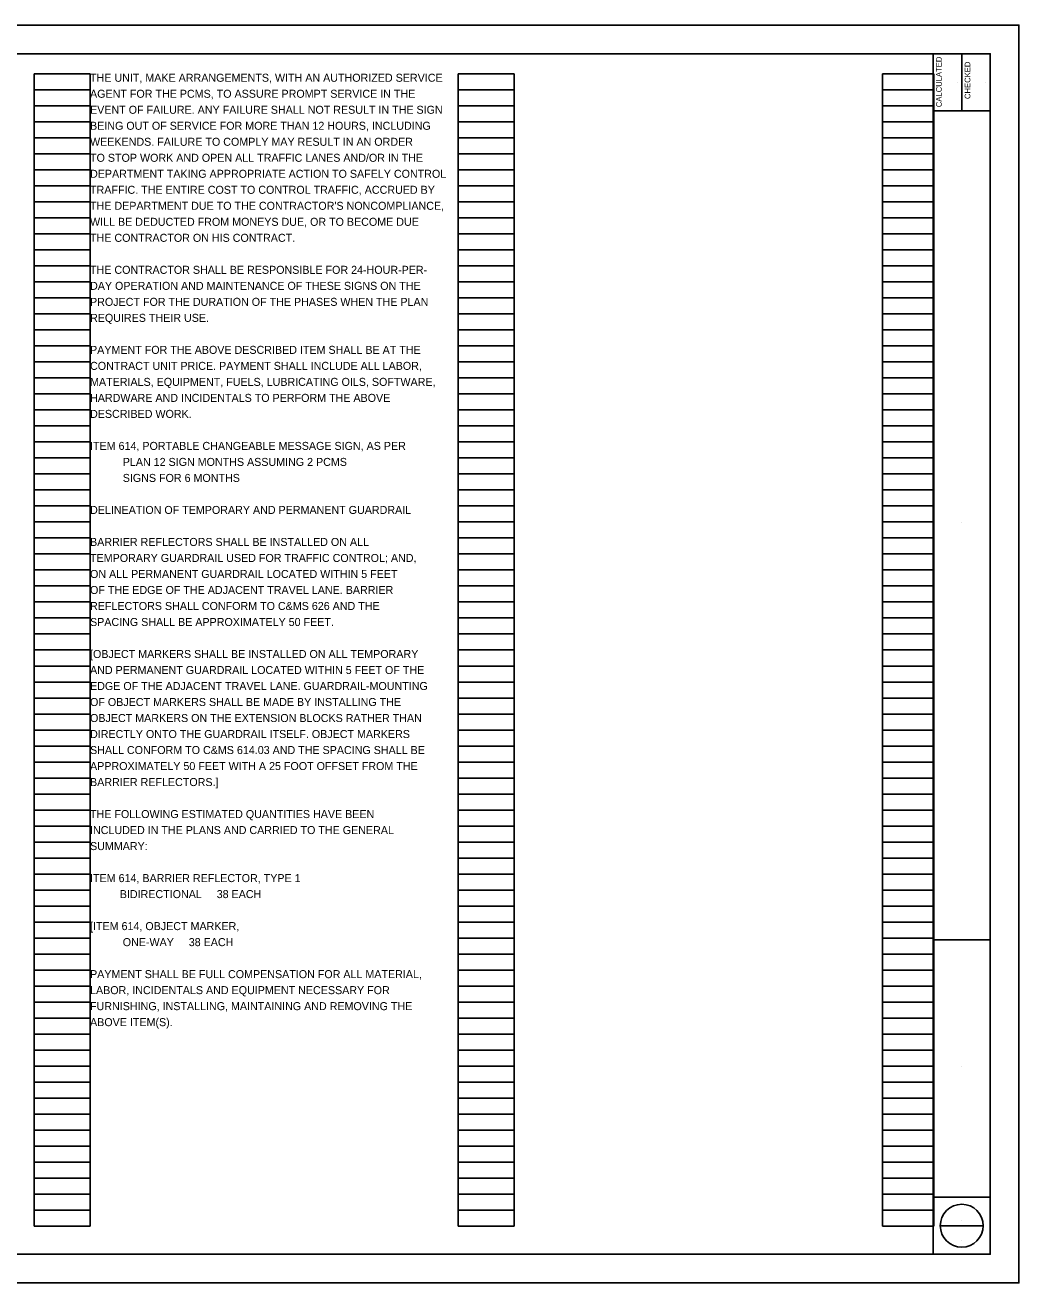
# Model space of a CAD drawing. Extents: x 0 to 34, y 0 to 22.
# Drawn here: x 16.62 to 34, y 0 to 22 of the extents above; entities that cross this region are included whole.
import ezdxf

# ---------------------------------------------------------------- set-up
doc = ezdxf.new("R2010")
doc.units = 0
for name, color, linetype in [('SH_Border', 7, 'Continuous'), ('SH_Cut_Line', 7, 'Continuous'), ('SH_Data', 7, 'Continuous'), ('SH_Text', 7, 'Continuous')]:
    doc.layers.add(name, color=color, linetype=linetype)

msp = doc.modelspace()

# ---------------------------------------------------------------- linework, layer by layer
at = {"layer": 'SH_Border'}
for p, q in [((32.5, 0.5), (32.5, 21.5)), ((33, 21.5), (33, 20.5)), ((32.5, 20.5), (33.5, 20.5)), ((32.5, 6), (33.5, 6)), ((32.5, 1.5), (33.5, 1.5))]:
    msp.add_line(p, q, dxfattribs=at)
msp.add_lwpolyline([(2, 21.5), (33.5, 21.5), (33.5, 0.5), (2, 0.5)], close=True, dxfattribs=at)
at = {"layer": 'SH_Cut_Line'}
msp.add_lwpolyline([(0, 0), (34, 0), (34, 22), (0, 22)], close=True, dxfattribs=at)
at = {"layer": 'SH_Data'}
for p, q in [((16.772, 0.99), (16.772, 21.15)), ((16.772, 21.15), (17.752, 21.15)), ((17.752, 0.99), (17.752, 21.15)), ((24.192, 0.99), (24.192, 21.15)), ((24.192, 21.15), (25.172, 21.15)), ((25.172, 0.99), (25.172, 21.15)), ((31.612, 0.99), (31.612, 21.15)), ((31.612, 21.15), (32.512, 21.15)), ((32.512, 0.99), (32.512, 21.15)), ((32.92, 21.004), (32.92, 21.004)), ((33.42, 21.004), (33.42, 21.004)), ((16.772, 20.87), (17.752, 20.87)), ((24.192, 20.87), (25.172, 20.87)), ((31.612, 20.87), (32.512, 20.87)), ((16.772, 20.59), (17.752, 20.59)), ((24.192, 20.59), (25.172, 20.59)), ((31.612, 20.59), (32.512, 20.59)), ((16.772, 20.31), (17.752, 20.31)), ((24.192, 20.31), (25.172, 20.31)), ((31.612, 20.31), (32.512, 20.31)), ((16.772, 20.03), (17.752, 20.03)), ((24.192, 20.03), (25.172, 20.03)), ((31.612, 20.03), (32.512, 20.03)), ((16.772, 19.75), (17.752, 19.75)), ((24.192, 19.75), (25.172, 19.75)), ((31.612, 19.75), (32.512, 19.75)), ((16.772, 19.47), (17.752, 19.47)), ((24.192, 19.47), (25.172, 19.47)), ((31.612, 19.47), (32.512, 19.47)), ((16.772, 19.19), (17.752, 19.19)), ((24.192, 19.19), (25.172, 19.19)), ((31.612, 19.19), (32.512, 19.19)), ((16.772, 18.91), (17.752, 18.91)), ((24.192, 18.91), (25.172, 18.91)), ((31.612, 18.91), (32.512, 18.91)), ((16.772, 18.63), (17.752, 18.63)), ((24.192, 18.63), (25.172, 18.63)), ((31.612, 18.63), (32.512, 18.63)), ((16.772, 18.35), (17.752, 18.35)), ((24.192, 18.35), (25.172, 18.35)), ((31.612, 18.35), (32.512, 18.35)), ((16.772, 18.07), (17.752, 18.07)), ((24.192, 18.07), (25.172, 18.07)), ((31.612, 18.07), (32.512, 18.07)), ((16.772, 17.79), (17.752, 17.79)), ((24.192, 17.79), (25.172, 17.79)), ((31.612, 17.79), (32.512, 17.79)), ((16.772, 17.51), (17.752, 17.51)), ((24.192, 17.51), (25.172, 17.51)), ((31.612, 17.51), (32.512, 17.51)), ((16.772, 17.23), (17.752, 17.23)), ((24.192, 17.23), (25.172, 17.23)), ((31.612, 17.23), (32.512, 17.23)), ((16.772, 16.95), (17.752, 16.95)), ((24.192, 16.95), (25.172, 16.95)), ((31.612, 16.95), (32.512, 16.95)), ((16.772, 16.67), (17.752, 16.67)), ((24.192, 16.67), (25.172, 16.67)), ((31.612, 16.67), (32.512, 16.67)), ((16.772, 16.39), (17.752, 16.39)), ((24.192, 16.39), (25.172, 16.39)), ((31.612, 16.39), (32.512, 16.39)), ((16.772, 16.11), (17.752, 16.11)), ((24.192, 16.11), (25.172, 16.11)), ((31.612, 16.11), (32.512, 16.11)), ((16.772, 15.83), (17.752, 15.83)), ((24.192, 15.83), (25.172, 15.83)), ((31.612, 15.83), (32.512, 15.83)), ((16.772, 15.55), (17.752, 15.55)), ((24.192, 15.55), (25.172, 15.55)), ((31.612, 15.55), (32.512, 15.55)), ((16.772, 15.27), (17.752, 15.27)), ((24.192, 15.27), (25.172, 15.27)), ((31.612, 15.27), (32.512, 15.27)), ((16.772, 14.99), (17.752, 14.99)), ((24.192, 14.99), (25.172, 14.99)), ((31.612, 14.99), (32.512, 14.99)), ((16.772, 14.71), (17.752, 14.71)), ((24.192, 14.71), (25.172, 14.71)), ((31.612, 14.71), (32.512, 14.71)), ((16.772, 14.43), (17.752, 14.43)), ((24.192, 14.43), (25.172, 14.43)), ((31.612, 14.43), (32.512, 14.43)), ((16.772, 14.15), (17.752, 14.15)), ((24.192, 14.15), (25.172, 14.15)), ((31.612, 14.15), (32.512, 14.15)), ((16.772, 13.87), (17.752, 13.87)), ((24.192, 13.87), (25.172, 13.87)), ((31.612, 13.87), (32.512, 13.87)), ((16.772, 13.59), (17.752, 13.59)), ((24.192, 13.59), (25.172, 13.59)), ((31.612, 13.59), (32.512, 13.59)), ((16.772, 13.31), (17.752, 13.31)), ((24.192, 13.31), (25.172, 13.31)), ((31.612, 13.31), (32.512, 13.31)), ((33, 13.292), (33, 13.292)), ((16.772, 13.03), (17.752, 13.03)), ((24.192, 13.03), (25.172, 13.03)), ((31.612, 13.03), (32.512, 13.03)), ((16.772, 12.75), (17.752, 12.75)), ((24.192, 12.75), (25.172, 12.75)), ((31.612, 12.75), (32.512, 12.75)), ((16.772, 12.47), (17.752, 12.47)), ((24.192, 12.47), (25.172, 12.47)), ((31.612, 12.47), (32.512, 12.47)), ((16.772, 12.19), (17.752, 12.19)), ((24.192, 12.19), (25.172, 12.19)), ((31.612, 12.19), (32.512, 12.19)), ((16.772, 11.91), (17.752, 11.91)), ((24.192, 11.91), (25.172, 11.91)), ((31.612, 11.91), (32.512, 11.91)), ((16.772, 11.63), (17.752, 11.63)), ((24.192, 11.63), (25.172, 11.63)), ((31.612, 11.63), (32.512, 11.63)), ((16.772, 11.35), (17.752, 11.35)), ((24.192, 11.35), (25.172, 11.35)), ((31.612, 11.35), (32.512, 11.35)), ((16.772, 11.07), (17.752, 11.07)), ((24.192, 11.07), (25.172, 11.07)), ((31.612, 11.07), (32.512, 11.07)), ((16.772, 10.79), (17.752, 10.79)), ((24.192, 10.79), (25.172, 10.79)), ((31.612, 10.79), (32.512, 10.79)), ((16.772, 10.51), (17.752, 10.51)), ((24.192, 10.51), (25.172, 10.51)), ((31.612, 10.51), (32.512, 10.51)), ((16.772, 10.23), (17.752, 10.23)), ((24.192, 10.23), (25.172, 10.23)), ((31.612, 10.23), (32.512, 10.23)), ((16.772, 9.95), (17.752, 9.95)), ((24.192, 9.95), (25.172, 9.95)), ((31.612, 9.95), (32.512, 9.95)), ((16.772, 9.67), (17.752, 9.67)), ((24.192, 9.67), (25.172, 9.67)), ((31.612, 9.67), (32.512, 9.67)), ((16.772, 9.39), (17.752, 9.39)), ((24.192, 9.39), (25.172, 9.39)), ((31.612, 9.39), (32.512, 9.39)), ((16.772, 9.11), (17.752, 9.11)), ((24.192, 9.11), (25.172, 9.11)), ((31.612, 9.11), (32.512, 9.11)), ((16.772, 8.83), (17.752, 8.83)), ((24.192, 8.83), (25.172, 8.83)), ((31.612, 8.83), (32.512, 8.83)), ((16.772, 8.55), (17.752, 8.55)), ((24.192, 8.55), (25.172, 8.55)), ((31.612, 8.55), (32.512, 8.55)), ((16.772, 8.27), (17.752, 8.27)), ((24.192, 8.27), (25.172, 8.27)), ((31.612, 8.27), (32.512, 8.27)), ((16.772, 7.99), (17.752, 7.99)), ((24.192, 7.99), (25.172, 7.99)), ((31.612, 7.99), (32.512, 7.99)), ((16.772, 7.71), (17.752, 7.71)), ((24.192, 7.71), (25.172, 7.71)), ((31.612, 7.71), (32.512, 7.71)), ((16.772, 7.43), (17.752, 7.43)), ((24.192, 7.43), (25.172, 7.43)), ((31.612, 7.43), (32.512, 7.43)), ((16.772, 7.15), (17.752, 7.15)), ((24.192, 7.15), (25.172, 7.15)), ((31.612, 7.15), (32.512, 7.15)), ((16.772, 6.87), (17.752, 6.87)), ((24.192, 6.87), (25.172, 6.87)), ((31.612, 6.87), (32.512, 6.87)), ((16.772, 6.59), (17.752, 6.59)), ((24.192, 6.59), (25.172, 6.59)), ((31.612, 6.59), (32.512, 6.59)), ((16.772, 6.31), (17.752, 6.31)), ((24.192, 6.31), (25.172, 6.31)), ((31.612, 6.31), (32.512, 6.31)), ((16.772, 6.03), (17.752, 6.03)), ((24.192, 6.03), (25.172, 6.03)), ((31.612, 6.03), (32.512, 6.03)), ((16.772, 5.75), (17.752, 5.75)), ((24.192, 5.75), (25.172, 5.75)), ((31.612, 5.75), (32.512, 5.75)), ((16.772, 5.47), (17.752, 5.47)), ((24.192, 5.47), (25.172, 5.47)), ((31.612, 5.47), (32.512, 5.47)), ((16.772, 5.19), (17.752, 5.19)), ((24.192, 5.19), (25.172, 5.19)), ((31.612, 5.19), (32.512, 5.19)), ((16.772, 4.91), (17.752, 4.91)), ((24.192, 4.91), (25.172, 4.91)), ((31.612, 4.91), (32.512, 4.91)), ((16.772, 4.63), (17.752, 4.63)), ((24.192, 4.63), (25.172, 4.63)), ((31.612, 4.63), (32.512, 4.63)), ((16.772, 4.35), (17.752, 4.35)), ((24.192, 4.35), (25.172, 4.35)), ((31.612, 4.35), (32.512, 4.35)), ((16.772, 4.07), (17.752, 4.07)), ((24.192, 4.07), (25.172, 4.07)), ((31.612, 4.07), (32.512, 4.07)), ((16.772, 3.79), (17.752, 3.79)), ((24.192, 3.79), (25.172, 3.79)), ((31.612, 3.79), (32.512, 3.79)), ((33, 3.792), (33, 3.792)), ((16.772, 3.51), (17.752, 3.51)), ((24.192, 3.51), (25.172, 3.51)), ((31.612, 3.51), (32.512, 3.51)), ((16.772, 3.23), (17.752, 3.23)), ((24.192, 3.23), (25.172, 3.23)), ((31.612, 3.23), (32.512, 3.23)), ((16.772, 2.95), (17.752, 2.95)), ((24.192, 2.95), (25.172, 2.95)), ((31.612, 2.95), (32.512, 2.95)), ((16.772, 2.67), (17.752, 2.67)), ((24.192, 2.67), (25.172, 2.67)), ((31.612, 2.67), (32.512, 2.67)), ((16.772, 2.39), (17.752, 2.39)), ((24.192, 2.39), (25.172, 2.39)), ((31.612, 2.39), (32.512, 2.39)), ((16.772, 2.11), (17.752, 2.11)), ((24.192, 2.11), (25.172, 2.11)), ((31.612, 2.11), (32.512, 2.11)), ((16.772, 1.83), (17.752, 1.83)), ((24.192, 1.83), (25.172, 1.83)), ((31.612, 1.83), (32.512, 1.83)), ((16.772, 1.55), (17.752, 1.55)), ((24.192, 1.55), (25.172, 1.55)), ((31.612, 1.55), (32.512, 1.55)), ((16.772, 1.27), (17.752, 1.27)), ((24.192, 1.27), (25.172, 1.27)), ((31.612, 1.27), (32.512, 1.27)), ((16.772, 0.99), (17.752, 0.99)), ((24.192, 0.99), (25.172, 0.99)), ((31.612, 0.99), (32.512, 0.99)), ((32.625, 1), (33.375, 1)), ((33, 1.085), (33, 1.085)), ((33, 0.745), (33, 0.745))]:
    msp.add_line(p, q, dxfattribs=at)
msp.add_circle((33, 1), 0.375, dxfattribs=at)

# ---------------------------------------------------------------- texts
for s, p in [('CALCULATED', (32.652, 20.565)), ('CHECKED', (33.152, 20.708))]:
    msp.add_text(s, height=0.1, rotation=90, dxfattribs=at).set_placement(p)
at = {"layer": 'SH_Text'}
for s, p in [('THE UNIT, MAKE ARRANGEMENTS, WITH AN AUTHORIZED SERVICE', (17.752, 21.01)), ('AGENT FOR THE PCMS, TO ASSURE PROMPT SERVICE IN THE', (17.752, 20.73)), ('EVENT OF FAILURE. ANY FAILURE SHALL NOT RESULT IN THE SIGN', (17.752, 20.45)), ('BEING OUT OF SERVICE FOR MORE THAN 12 HOURS, INCLUDING', (17.752, 20.17)), ('WEEKENDS. FAILURE TO COMPLY MAY RESULT IN AN ORDER', (17.752, 19.89)), ('TO STOP WORK AND OPEN ALL TRAFFIC LANES AND/OR IN THE', (17.752, 19.61)), ('DEPARTMENT TAKING APPROPRIATE ACTION TO SAFELY CONTROL', (17.752, 19.33)), ('TRAFFIC. THE ENTIRE COST TO CONTROL TRAFFIC, ACCRUED BY', (17.752, 19.05)), ("THE DEPARTMENT DUE TO THE CONTRACTOR'S NONCOMPLIANCE,", (17.752, 18.77)), ('WILL BE DEDUCTED FROM MONEYS DUE, OR TO BECOME DUE', (17.752, 18.49)), ('THE CONTRACTOR ON HIS CONTRACT.', (17.752, 18.21)), ('THE CONTRACTOR SHALL BE RESPONSIBLE FOR 24-HOUR-PER-', (17.752, 17.65)), ('DAY OPERATION AND MAINTENANCE OF THESE SIGNS ON THE', (17.752, 17.37)), ('PROJECT FOR THE DURATION OF THE PHASES WHEN THE PLAN', (17.752, 17.09)), ('REQUIRES THEIR USE.', (17.752, 16.81)), ('PAYMENT FOR THE ABOVE DESCRIBED ITEM SHALL BE AT THE', (17.752, 16.25)), ('CONTRACT UNIT PRICE. PAYMENT SHALL INCLUDE ALL LABOR,', (17.752, 15.97)), ('MATERIALS, EQUIPMENT, FUELS, LUBRICATING OILS, SOFTWARE,', (17.752, 15.69)), ('HARDWARE AND INCIDENTALS TO PERFORM THE ABOVE', (17.752, 15.41)), ('DESCRIBED WORK.', (17.752, 15.13)), ('ITEM 614, PORTABLE CHANGEABLE MESSAGE SIGN, AS PER', (17.752, 14.57)), ('           PLAN 12 SIGN MONTHS ASSUMING 2 PCMS', (17.752, 14.29)), ('           SIGNS FOR 6 MONTHS', (17.752, 14.01)), ('DELINEATION OF TEMPORARY AND PERMANENT GUARDRAIL', (17.752, 13.45)), ('BARRIER REFLECTORS SHALL BE INSTALLED ON ALL', (17.752, 12.89)), ('TEMPORARY GUARDRAIL USED FOR TRAFFIC CONTROL; AND,', (17.752, 12.61)), ('ON ALL PERMANENT GUARDRAIL LOCATED WITHIN 5 FEET', (17.752, 12.33)), ('OF THE EDGE OF THE ADJACENT TRAVEL LANE. BARRIER', (17.752, 12.05)), ('REFLECTORS SHALL CONFORM TO C&MS 626 AND THE', (17.752, 11.77)), ('SPACING SHALL BE APPROXIMATELY 50 FEET.', (17.752, 11.49)), ('[OBJECT MARKERS SHALL BE INSTALLED ON ALL TEMPORARY', (17.752, 10.93)), ('AND PERMANENT GUARDRAIL LOCATED WITHIN 5 FEET OF THE', (17.752, 10.65)), ('EDGE OF THE ADJACENT TRAVEL LANE. GUARDRAIL-MOUNTING', (17.752, 10.37)), ('OF OBJECT MARKERS SHALL BE MADE BY INSTALLING THE', (17.752, 10.09)), ('OBJECT MARKERS ON THE EXTENSION BLOCKS RATHER THAN', (17.752, 9.81)), ('DIRECTLY ONTO THE GUARDRAIL ITSELF. OBJECT MARKERS', (17.752, 9.53)), ('SHALL CONFORM TO C&MS 614.03 AND THE SPACING SHALL BE', (17.752, 9.25)), ('APPROXIMATELY 50 FEET WITH A 25 FOOT OFFSET FROM THE', (17.752, 8.97)), ('BARRIER REFLECTORS.]', (17.752, 8.69)), ('THE FOLLOWING ESTIMATED QUANTITIES HAVE BEEN', (17.752, 8.13)), ('INCLUDED IN THE PLANS AND CARRIED TO THE GENERAL', (17.752, 7.85)), ('SUMMARY:', (17.752, 7.57)), ('ITEM 614, BARRIER REFLECTOR, TYPE 1', (17.752, 7.01)), ('          BIDIRECTIONAL     38 EACH', (17.752, 6.73)), ('[ITEM 614, OBJECT MARKER,', (17.752, 6.17)), ('           ONE-WAY     38 EACH', (17.752, 5.89)), ('PAYMENT SHALL BE FULL COMPENSATION FOR ALL MATERIAL,', (17.752, 5.33)), ('LABOR, INCIDENTALS AND EQUIPMENT NECESSARY FOR', (17.752, 5.05)), ('FURNISHING, INSTALLING, MAINTAINING AND REMOVING THE', (17.752, 4.77)), ('ABOVE ITEM(S).', (17.752, 4.49))]:
    msp.add_text(s, height=0.14, dxfattribs=at).set_placement(p)

doc.saveas('drawing.dxf')
